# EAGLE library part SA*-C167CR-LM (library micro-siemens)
16bit Microcontroller
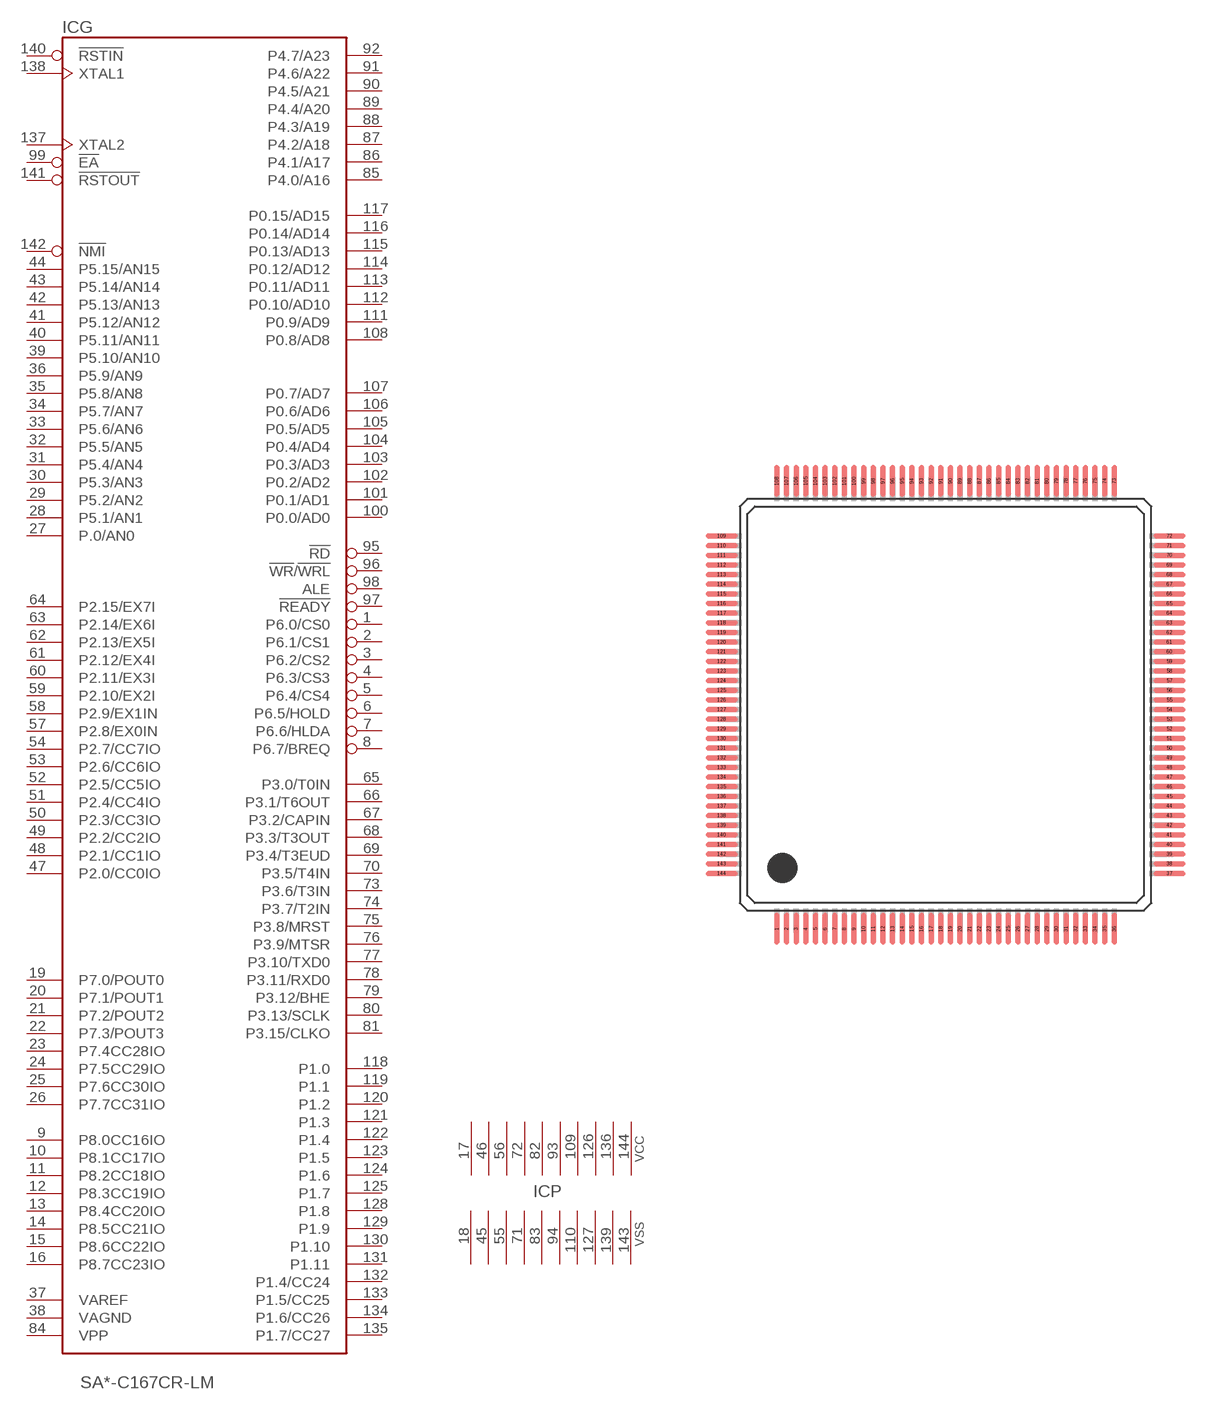
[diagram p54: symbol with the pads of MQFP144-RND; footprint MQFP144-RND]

Designator prefix IC; gates G=C167-1-1 P=10VCCVSS-1

## SAB-C167CR-LM (OC_FARNELL: unknown; OC_NEWARK: unknown), SAF-C167CR-LM (OC_FARNELL: unknown; OC_NEWARK: unknown), SAK-C167CR-LM (MPN: SAK-C167CR-LM HA; OC_FARNELL: 1220083; OC_NEWARK: 24M7191)  [MQFP144-RND]
1  G:P6.0/CS0
2  G:P6.1/CS1
3  G:P6.2/CS2
4  G:P6.3/CS3
5  G:P6.4/CS4
6  G:P6.5/HOLD
7  G:P6.6/HLDA
8  G:P6.7/BREQ
9  G:P8.0CC16IO
10  G:P8.1CC17IO
11  G:P8.2CC18IO
12  G:P8.3CC19IO
13  G:P8.4CC20IO
14  G:P8.5CC21IO
15  G:P8.6CC22IO
16  G:P8.7CC23IO
17  P:VCC  pwr
18  P:VSS  pwr
19  G:P7.0/POUT0
20  G:P7.1/POUT1
21  G:P7.2/POUT2
22  G:P7.3/POUT3
23  G:P7.4CC28IO
24  G:P7.5CC29IO
25  G:P7.6CC30IO
26  G:P7.7CC31IO
27  G:P.0/AN0  in
28  G:P5.1/AN1  in
29  G:P5.2/AN2  in
30  G:P5.3/AN3  in
31  G:P5.4/AN4  in
32  G:P5.5/AN5  in
33  G:P5.6/AN6  in
34  G:P5.7/AN7  in
35  G:P5.8/AN8  in
36  G:P5.9/AN9  in
37  G:VAREF  pas
38  G:VAGND  pas
39  G:P5.10/AN10  in
40  G:P5.11/AN11  in
41  G:P5.12/AN12  in
42  G:P5.13/AN13  in
43  G:P5.14/AN14  in
44  G:P5.15/AN15  in
45  P:VSS  pwr
46  P:VCC  pwr
47  G:P2.0/CC0IO
48  G:P2.1/CC1IO
49  G:P2.2/CC2IO
50  G:P2.3/CC3IO
51  G:P2.4/CC4IO
52  G:P2.5/CC5IO
53  G:P2.6/CC6IO
54  G:P2.7/CC7IO
55  P:VSS  pwr
56  P:VCC  pwr
57  G:P2.8/EX0IN
58  G:P2.9/EX1IN
59  G:P2.10/EX2I
60  G:P2.11/EX3I
61  G:P2.12/EX4I
62  G:P2.13/EX5I
63  G:P2.14/EX6I
64  G:P2.15/EX7I
65  G:P3.0/T0IN
66  G:P3.1/T6OUT
67  G:P3.2/CAPIN
68  G:P3.3/T3OUT
69  G:P3.4/T3EUD
70  G:P3.5/T4IN
71  P:VSS  pwr
72  P:VCC  pwr
73  G:P3.6/T3IN
74  G:P3.7/T2IN
75  G:P3.8/MRST
76  G:P3.9/MTSR
77  G:P3.10/TXD0
78  G:P3.11/RXD0
79  G:P3.12/BHE
80  G:P3.13/SCLK
81  G:P3.15/CLKO
82  P:VCC  pwr
83  P:VSS  pwr
84  G:VPP  pas
85  G:P4.0/A16
86  G:P4.1/A17
87  G:P4.2/A18
88  G:P4.3/A19
89  G:P4.4/A20
90  G:P4.5/A21
91  G:P4.6/A22
92  G:P4.7/A23
93  P:VCC  pwr
94  P:VSS  pwr
95  G:!RD  out
96  G:!WR!/!WRL  out
97  G:!READY  in
98  G:ALE  out
99  G:!EA  in
100  G:P0.0/AD0
101  G:P0.1/AD1
102  G:P0.2/AD2
103  G:P0.3/AD3
104  G:P0.4/AD4
105  G:P0.5/AD5
106  G:P0.6/AD6
107  G:P0.7/AD7
108  G:P0.8/AD8
109  P:VCC  pwr
110  P:VSS  pwr
111  G:P0.9/AD9
112  G:P0.10/AD10
113  G:P0.11/AD11
114  G:P0.12/AD12
115  G:P0.13/AD13
116  G:P0.14/AD14
117  G:P0.15/AD15
118  G:P1.0
119  G:P1.1
120  G:P1.2
121  G:P1.3
122  G:P1.4
123  G:P1.5
124  G:P1.6
125  G:P1.7
126  P:VCC  pwr
127  P:VSS  pwr
128  G:P1.8
129  G:P1.9
130  G:P1.10
131  G:P1.11
132  G:P1.4/CC24
133  G:P1.5/CC25
134  G:P1.6/CC26
135  G:P1.7/CC27
136  P:VCC  pwr
137  G:XTAL2  out
138  G:XTAL1  in
139  P:VSS  pwr
140  G:!RSTIN  in
141  G:!RSTOUT  out
142  G:!NMI  in
143  P:VSS  pwr
144  P:VCC  pwr

## Footprint MQFP144-RND (pad centres in mm)
Metric Quad Flat Pack with rounded pads
smd 0.35 x 2.2: 1 -11.375,-15.1; 2 -10.725,-15.1; 3 -10.075,-15.1; 4 -9.425,-15.1; 5 -8.775,-15.1; 6 -8.125,-15.1; 7 -7.475,-15.1; 8 -6.825,-15.1; 9 -6.175,-15.1; 10 -5.525,-15.1; 11 -4.875,-15.1; 12 -4.225,-15.1; 13 -3.575,-15.1; 14 -2.925,-15.1; 15 -2.275,-15.1; 16 -1.625,-15.1; 17 -0.975,-15.1; 18 -0.325,-15.1; 19 0.325,-15.1; 20 0.975,-15.1; 21 1.625,-15.1; 22 2.275,-15.1; 23 2.925,-15.1; 24 3.575,-15.1; 25 4.225,-15.1; 26 4.875,-15.1; 27 5.525,-15.1; 28 6.175,-15.1; 29 6.825,-15.1; 30 7.475,-15.1; 31 8.125,-15.1; 32 8.775,-15.1; 33 9.425,-15.1; 34 10.075,-15.1; 35 10.725,-15.1; 36 11.375,-15.1; 73 11.375,15.1; 74 10.725,15.1; 75 10.075,15.1; 76 9.425,15.1; 77 8.775,15.1; 78 8.125,15.1; 79 7.475,15.1; 80 6.825,15.1; 81 6.175,15.1; 82 5.525,15.1; 83 4.875,15.1; 84 4.225,15.1; 85 3.575,15.1; 86 2.925,15.1; 87 2.275,15.1; 88 1.625,15.1; 89 0.975,15.1; 90 0.325,15.1; 91 -0.325,15.1; 92 -0.975,15.1; 93 -1.625,15.1; 94 -2.275,15.1; 95 -2.925,15.1; 96 -3.575,15.1; 97 -4.225,15.1; 98 -4.875,15.1; 99 -5.525,15.1; 100 -6.175,15.1; 101 -6.825,15.1; 102 -7.475,15.1; 103 -8.125,15.1; 104 -8.775,15.1; 105 -9.425,15.1; 106 -10.075,15.1; 107 -10.725,15.1; 108 -11.375,15.1
smd 2.2 x 0.35: 37 15.1,-11.375; 38 15.1,-10.725; 39 15.1,-10.075; 40 15.1,-9.425; 41 15.1,-8.775; 42 15.1,-8.125; 43 15.1,-7.475; 44 15.1,-6.825; 45 15.1,-6.175; 46 15.1,-5.525; 47 15.1,-4.875; 48 15.1,-4.225; 49 15.1,-3.575; 50 15.1,-2.925; 51 15.1,-2.275; 52 15.1,-1.625; 53 15.1,-0.975; 54 15.1,-0.325; 55 15.1,0.325; 56 15.1,0.975; 57 15.1,1.625; 58 15.1,2.275; 59 15.1,2.925; 60 15.1,3.575; 61 15.1,4.225; 62 15.1,4.875; 63 15.1,5.525; 64 15.1,6.175; 65 15.1,6.825; 66 15.1,7.475; 67 15.1,8.125; 68 15.1,8.775; 69 15.1,9.425; 70 15.1,10.075; 71 15.1,10.725; 72 15.1,11.375; 109 -15.1,11.375; 110 -15.1,10.725; 111 -15.1,10.075; 112 -15.1,9.425; 113 -15.1,8.775; 114 -15.1,8.125; 115 -15.1,7.475; 116 -15.1,6.825; 117 -15.1,6.175; 118 -15.1,5.525; 119 -15.1,4.875; 120 -15.1,4.225; 121 -15.1,3.575; 122 -15.1,2.925; 123 -15.1,2.275; 124 -15.1,1.625; 125 -15.1,0.975; 126 -15.1,0.325; 127 -15.1,-0.325; 128 -15.1,-0.975; 129 -15.1,-1.625; 130 -15.1,-2.275; 131 -15.1,-2.925; 132 -15.1,-3.575; 133 -15.1,-4.225; 134 -15.1,-4.875; 135 -15.1,-5.525; 136 -15.1,-6.175; 137 -15.1,-6.825; 138 -15.1,-7.475; 139 -15.1,-8.125; 140 -15.1,-8.775; 141 -15.1,-9.425; 142 -15.1,-10.075; 143 -15.1,-10.725; 144 -15.1,-11.375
